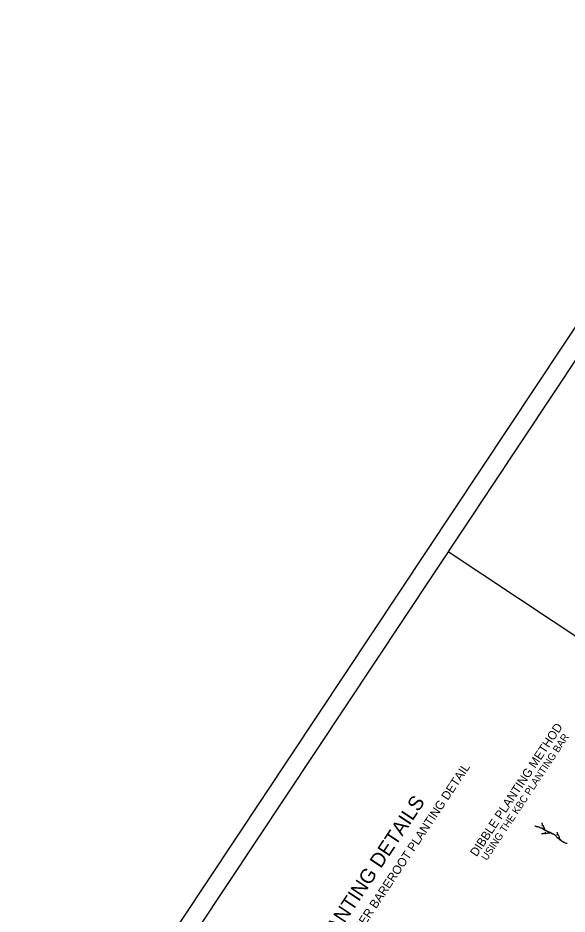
# Model space of a CAD drawing. Extents: x 561231 to 564240, y 590260 to 602519.
# Drawn here: x 563134 to 563537, y 590808 to 591465 of the extents above; entities that cross this region are included whole.
import ezdxf

# ---------------------------------------------------------------- set-up
doc = ezdxf.new("R2010")
doc.units = 0
doc.layers.add('Old_Level_1', color=7, linetype='Continuous')
doc.layers.add('Sheet Plot Border Outside CELL', color=7, linetype='Continuous')

msp = doc.modelspace()

# ---------------------------------------------------------------- linework, layer by layer
at = {"layer": 'Old_Level_1'}
msp.add_line((563974.32, 590725.26), (563449.32, 591073.51), dxfattribs=at)
msp.add_lwpolyline([(563698.59, 591448.69), (563200.53, 590699.06), (563725.27, 590350.42), (564223.33, 591100.04)], close=True, dxfattribs=at)
for points in [[(563515.01, 590872.19), (563514.83, 590872.17), (563514.76, 590872.16), (563514.68, 590872.14), (563514.55, 590872.16), (563514.45, 590872.09), (563514.37, 590872.08), (563514.28, 590872.14), (563514.2, 590872.13), (563514.11, 590872.19), (563514.04, 590872.3), (563513.95, 590872.36), (563513.87, 590872.34), (563513.75, 590872.36), (563513.61, 590872.45), (563513.52, 590872.51), (563513.42, 590872.57), (563513.33, 590872.63), (563513.24, 590872.7), (563513.13, 590872.63), (563513.05, 590872.62), (563512.97, 590872.6)], [(563514.64, 590872.44), (563515.01, 590872.19), (563515.2, 590872.07), (563515.38, 590871.95), (563515.51, 590872.13), (563515.69, 590872.01), (563515.82, 590872.2), (563516, 590872.07), (563516.19, 590871.95), (563516.38, 590871.82), (563516.56, 590871.7), (563516.75, 590871.58), (563516.94, 590871.45), (563517.12, 590871.33), (563517.25, 590871.52), (563517.43, 590871.39), (563517.74, 590871.45), (563517.93, 590871.33), (563518.05, 590871.52), (563518.24, 590871.39), (563518.42, 590871.27), (563518.61, 590871.15), (563518.8, 590871.02), (563518.86, 590870.71), (563519.05, 590870.59), (563519.23, 590870.47), (563519.42, 590870.34), (563519.6, 590870.22), (563519.79, 590870.1), (563519.98, 590869.97), (563520.16, 590869.85), (563520.35, 590869.72), (563520.54, 590869.6), (563520.72, 590869.48), (563521.03, 590869.54), (563521.22, 590869.42), (563521.41, 590869.29), (563521.59, 590869.17), (563521.78, 590869.04), (563521.96, 590868.92), (563522.28, 590868.98), (563522.46, 590868.86), (563522.65, 590868.74), (563522.83, 590868.61), (563523.02, 590868.49), (563523.33, 590868.55), (563523.7, 590868.31), (563523.83, 590868.49), (563524.01, 590868.37), (563524.2, 590868.24), (563524.39, 590868.12), (563524.57, 590868), (563524.94, 590867.75), (563525.32, 590867.5), (563525.88, 590867.13), (563526.37, 590867.07), (563526.56, 590866.95), (563526.75, 590866.82), (563526.93, 590866.7), (563527.12, 590866.58), (563527.31, 590866.45), (563527.49, 590866.33), (563527.68, 590866.21), (563527.86, 590866.08), (563528.05, 590865.96), (563528.24, 590865.83), (563528.3, 590865.52), (563528.67, 590865.28), (563528.92, 590864.84), (563529.11, 590864.72), (563529.29, 590864.6), (563529.17, 590864.41), (563529.36, 590864.29), (563529.54, 590864.16), (563529.73, 590864.04), (563529.92, 590863.92), (563530.1, 590863.79), (563530.29, 590863.67), (563530.48, 590863.54), (563530.66, 590863.42), (563530.72, 590863.11), (563530.91, 590862.99), (563531.1, 590862.86), (563531.28, 590862.74), (563531.47, 590862.62), (563531.66, 590862.49), (563531.84, 590862.37), (563532.03, 590862.25), (563532.22, 590862.12), (563532.59, 590861.87), (563532.77, 590861.75), (563532.96, 590861.63), (563533.33, 590861.38), (563533.52, 590861.26), (563533.71, 590861.13), (563533.89, 590861.01), (563534.2, 590861.07), (563534.39, 590860.95), (563534.58, 590860.82), (563534.76, 590860.7), (563535.13, 590860.45)], [(563520.22, 590870.34), (563519.29, 590872.57), (563519.1, 590872.7), (563519.23, 590872.88), (563519.04, 590873.01), (563518.92, 590872.82), (563518.73, 590872.95), (563518.54, 590873.07), (563518.36, 590873.19), (563518.23, 590873.01), (563518.05, 590873.13)], [(563519.23, 590872.88), (563518.67, 590873.26), (563518.48, 590873.38), (563518.6, 590873.56), (563518.54, 590873.87), (563518.48, 590874.18), (563518.42, 590874.49), (563518.23, 590874.62), (563518.35, 590874.8), (563518.17, 590874.93)], [(563521.16, 590867.31), (563521.13, 590867.4), (563520.91, 590867.27), (563520.83, 590867.26), (563520.72, 590867.19), (563520.65, 590867.18), (563520.54, 590867.12), (563520.46, 590867.1), (563520.37, 590867.16), (563520.27, 590867.22), (563520.2, 590867.21), (563520.1, 590867.27), (563520.03, 590867.25), (563519.9, 590867.27), (563519.82, 590867.25), (563519.75, 590867.24), (563519.67, 590867.22), (563519.54, 590867.24), (563519.39, 590867.21), (563519.23, 590867.17), (563519.08, 590867.14), (563519, 590867.13), (563518.89, 590867.07), (563518.77, 590867.08), (563518.69, 590867.07), (563518.61, 590867.05), (563518.52, 590866.91), (563518.54, 590866.83), (563518.44, 590866.89), (563518.27, 590866.94), (563518.18, 590867), (563518.09, 590867.06), (563517.99, 590867.13), (563517.92, 590867.11)], [(563524.64, 590867.69), (563524.32, 590867.62), (563524.2, 590867.44), (563524.02, 590867.56), (563523.83, 590867.69), (563523.71, 590867.5), (563523.52, 590867.62), (563523.21, 590867.56), (563523.02, 590867.68), (563522.9, 590867.5), (563522.71, 590867.62), (563522.4, 590867.56), (563522.28, 590867.37), (563521.97, 590867.31), (563521.78, 590867.43), (563521.47, 590867.37), (563521.16, 590867.31), (563520.98, 590867.43), (563520.79, 590867.55), (563520.91, 590867.74), (563520.73, 590867.86), (563520.6, 590867.68), (563520.42, 590867.8), (563520.29, 590867.62), (563520.11, 590867.74), (563519.98, 590867.55)], [(563520.22, 590870.34), (563520.29, 590870.3), (563520.3, 590870.22), (563520.32, 590870.15), (563520.38, 590870.04), (563520.48, 590869.98), (563520.57, 590869.91), (563520.63, 590869.8), (563520.72, 590869.74), (563520.82, 590869.68), (563520.91, 590869.62), (563520.93, 590869.54), (563521.02, 590869.48)], [(563524.64, 590867.69), (563524.89, 590867.52), (563524.98, 590867.46), (563525.06, 590867.47), (563525.15, 590867.41), (563525.24, 590867.35), (563525.34, 590867.29), (563525.41, 590867.3), (563525.51, 590867.24), (563525.6, 590867.18)], [(563531.34, 590863.24), (563531.03, 590863.98), (563530.97, 590864.29), (563530.91, 590864.6), (563530.72, 590864.72), (563530.84, 590864.91), (563530.66, 590865.03), (563530.59, 590865.34), (563530.41, 590865.47), (563530.53, 590865.65), (563530.35, 590865.78), (563530.16, 590865.9), (563529.97, 590866.02), (563529.79, 590866.15), (563529.6, 590866.27), (563529.41, 590866.39), (563529.23, 590866.52), (563529.1, 590866.33)], [(563530.1, 590866.21), (563529.72, 590867.26), (563529.54, 590867.39), (563529.66, 590867.57), (563529.47, 590867.7), (563529.41, 590868.01), (563529.22, 590868.13), (563529.35, 590868.32)], [(563530.1, 590866.21), (563530.14, 590866.11), (563530.15, 590866.03), (563530.25, 590865.97)], [(563531.34, 590863.24), (563531.49, 590863.21), (563531.5, 590863.13), (563531.59, 590863.07), (563531.61, 590862.99), (563531.67, 590862.88), (563531.69, 590862.81), (563531.7, 590862.73), (563531.72, 590862.65), (563531.81, 590862.59), (563531.83, 590862.51), (563531.84, 590862.43)], [(563535.13, 590860.45), (563535.82, 590860.27), (563536, 590860.15), (563536.31, 590860.21), (563536.69, 590859.96)]]:
    msp.add_lwpolyline(points, dxfattribs=at)
at = {"layer": 'Sheet Plot Border Outside CELL'}
msp.add_lwpolyline([(563681.23, 590259.74), (564240.22, 591101.07), (563692.99, 591464.65), (563134, 590623.32)], close=True, dxfattribs=at)

# ---------------------------------------------------------------- texts
at = {"layer": 'Old_Level_1'}
for s, height, p in [('DIBBLE PLANTING METHOD', 6.3779, (563470.26, 590849.87)), ('USING THE KBC PLANTING BAR', 5.315, (563477.73, 590847.05)), ('SEEDLING /   LINER BAREROOT PLANTING DETAIL', 6.3779, (563350.94, 590743.06)), ('PLANTING DETAILS', 10.6299, (563358.54, 590778.63))]:
    msp.add_text(s, height=height, rotation=56.44242, dxfattribs=at).set_placement(p)

doc.saveas('drawing.dxf')
